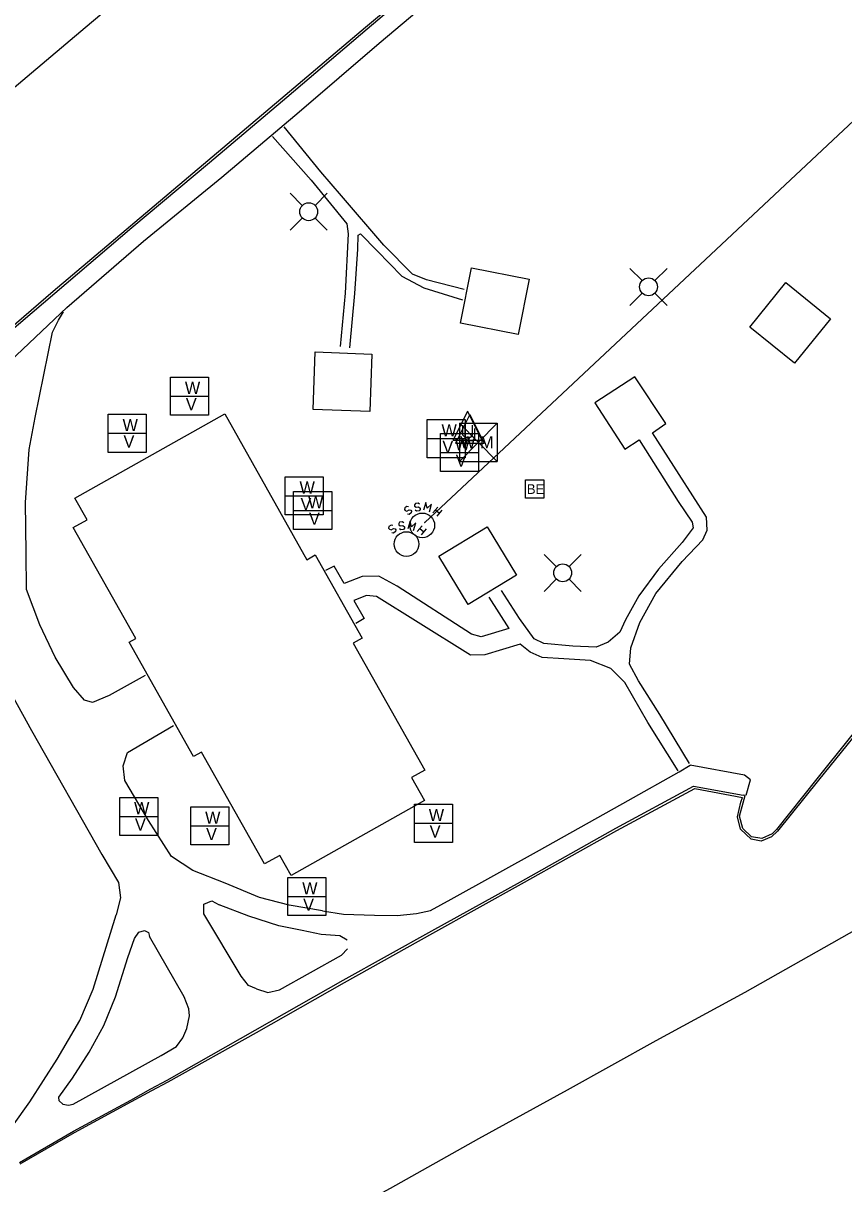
# Model space of a CAD drawing. Extents: x 1042086 to 1119166, y 1916606 to 1927565.
# Drawn here: x 1043119 to 1043321.6, y 1926246.9 to 1926533.5 of the extents above; entities that cross this region are included whole.
import ezdxf

# ---------------------------------------------------------------- set-up
doc = ezdxf.new("R2010")
doc.units = 0
for name, color, linetype in [('S_BUILDING', 7, 'Continuous'), ('S_CURB', 7, 'Continuous'), ('S_EDGE_PAVEMENT', 7, 'Continuous'), ('S_ELECTRIC_UTILITIES', 7, 'Continuous'), ('S_SANITARY_SEWER', 7, 'Continuous'), ('S_SIDEWALK', 7, 'Continuous'), ('S_UNDERGROUND_CABLE', 7, 'Continuous'), ('S_UTILITY_POLE', 7, 'Continuous'), ('S_UTL_PT_SYM', 7, 'Continuous'), ('S_WATER_UTILITIES', 7, 'Continuous')]:
    doc.layers.add(name, color=color, linetype=linetype)

msp = doc.modelspace()

# ---------------------------------------------------------------- linework, layer by layer
at = {"layer": 'S_BUILDING'}
for points in [[(1043241.2, 1926456.64), (1043226.98, 1926459.44), (1043229.68, 1926473.11), (1043243.9, 1926470.3)], [(1043309.4, 1926449.49), (1043298.39, 1926458.39), (1043307.29, 1926469.41), (1043318.31, 1926460.51)], [(1043190.58, 1926438.1), (1043191.11, 1926452.32), (1043205.08, 1926451.79), (1043204.55, 1926437.58)], [(1043178.6, 1926325.86), (1043163.01, 1926353.51), (1043161.04, 1926352.4), (1043145.14, 1926380.6), (1043146.84, 1926381.56), (1043131.39, 1926408.96), (1043134.77, 1926410.87), (1043131.79, 1926416.16), (1043168.75, 1926437), (1043189.05, 1926400.99), (1043191.11, 1926402.16), (1043202.7, 1926381.61), (1043200.48, 1926380.35), (1043218.14, 1926349.04), (1043214.89, 1926347.21), (1043218.08, 1926341.56), (1043185.15, 1926322.99), (1043182.34, 1926327.96)], [(1043228.86, 1926389.91), (1043221.62, 1926401.87), (1043233.58, 1926409.1), (1043240.82, 1926397.15)]]:
    msp.add_lwpolyline(points, close=True, dxfattribs=at)
at = {"layer": 'S_CURB'}
for points in [[(1043112.19, 1926454.4), (1043126.79, 1926466.85), (1043145.84, 1926483.04), (1043164.98, 1926499.12), (1043184.11, 1926515.22), (1043203.91, 1926532.06), (1043222.97, 1926548.25)], [(1043366.1, 1926416.39), (1043367.26, 1926414.66), (1043367.55, 1926413.33), (1043367.41, 1926412.29), (1043361.98, 1926405.29), (1043346.23, 1926385.88), (1043330.59, 1926366.38), (1043314.91, 1926346.91), (1043304.94, 1926334.4), (1043303.88, 1926333.32), (1043301.33, 1926332.15), (1043298.81, 1926332.56), (1043296.65, 1926334.61), (1043295.87, 1926337.66), (1043296.75, 1926340.95), (1043297.22, 1926342.73), (1043296.76, 1926342.83)], [(1043118.12, 1926252.12), (1043131.43, 1926259.9), (1043145.56, 1926267.51), (1043150.56, 1926270.32), (1043154.54, 1926272.51), (1043176.31, 1926284.81), (1043198.04, 1926297.17), (1043219.85, 1926309.38), (1043241.76, 1926321.41), (1043265.27, 1926334.69), (1043284.45, 1926345.09), (1043296.76, 1926342.83)]]:
    msp.add_lwpolyline(points, dxfattribs=at)
at = {"layer": 'S_EDGE_PAVEMENT'}
for points in [[(1042885.56, 1926337.32), (1042899.04, 1926343.23), (1042920.21, 1926356.51), (1042940.86, 1926370.65), (1042959.18, 1926385.04), (1042978.59, 1926400.81), (1042997.79, 1926416.81), (1043019.29, 1926434.74), (1043038.53, 1926450.69), (1043056.99, 1926467.43), (1043076.46, 1926483.12), (1043095.44, 1926499.39), (1043115.21, 1926516.28), (1043134.32, 1926532.4), (1043153.39, 1926548.56)], [(1043111.86, 1926454.8), (1043126.38, 1926467.34), (1043145.47, 1926483.48), (1043183.68, 1926515.73), (1043203.53, 1926532.51), (1043222.69, 1926548.57)], [(1043366.61, 1926416.77), (1043367.8, 1926415.07), (1043368.17, 1926413.35), (1043368.1, 1926412.3), (1043362.43, 1926404.93), (1043346.84, 1926385.39), (1043331.05, 1926366), (1043315.37, 1926346.53), (1043305.25, 1926333.99), (1043303.73, 1926332.56), (1043301.19, 1926331.5), (1043298.69, 1926331.97), (1043296.12, 1926334.45), (1043295.32, 1926337.5), (1043296.15, 1926341.11), (1043296.56, 1926342.25)], [(1043102.91, 1926186.56), (1043122.35, 1926197.07), (1043144.15, 1926209.32), (1043166.01, 1926221.45), (1043187.73, 1926233.83), (1043209.7, 1926245.77), (1043231.46, 1926258.09), (1043253.4, 1926270.06), (1043275.25, 1926282.23), (1043297.21, 1926294.17), (1043326.74, 1926310.95), (1043348.54, 1926323.19), (1043370.32, 1926335.48), (1043392.17, 1926347.63), (1043414.02, 1926359.78), (1043436.24, 1926372.23), (1043453.57, 1926381.87)], [(1043118.3, 1926251.81), (1043131.64, 1926259.54), (1043145.75, 1926267.17), (1043150.77, 1926269.93), (1043154.77, 1926272.1), (1043176.6, 1926284.28), (1043198.37, 1926296.56), (1043220.17, 1926308.81), (1043242.01, 1926320.95), (1043265.57, 1926334.14), (1043284.77, 1926344.5), (1043296.56, 1926342.25)]]:
    msp.add_lwpolyline(points, dxfattribs=at)
at = {"layer": 'S_ELECTRIC_UTILITIES'}
msp.add_lwpolyline([(1043243.03, 1926416.19), (1043243.03, 1926420.69), (1043247.53, 1926420.69), (1043247.53, 1926416.19)], close=True, dxfattribs=at)
at = {"layer": 'S_SANITARY_SEWER'}
for p, q in [((1043379.23, 1926561.23), (1043218.13, 1926410.22)), ((1043213.19, 1926413.78), (1043213.12, 1926413.39)), ((1043213.12, 1926413.39), (1043213.31, 1926413.12)), ((1043213.74, 1926414.17), (1043213.19, 1926413.78)), ((1043213.31, 1926413.12), (1043213.74, 1926413)), ((1043214.16, 1926414.09), (1043213.74, 1926414.17)), ((1043213.74, 1926413), (1043214.28, 1926413.35)), ((1043214.28, 1926412.19), (1043213.89, 1926412.27)), ((1043214.28, 1926413.35), (1043214.74, 1926413.27)), ((1043214.82, 1926412.58), (1043214.28, 1926412.19)), ((1043214.74, 1926413.27), (1043214.9, 1926413)), ((1043214.9, 1926413), (1043214.82, 1926412.58)), ((1043220.17, 1926412.54), (1043221.41, 1926414.01)), ((1043220.83, 1926413.31), (1043221.8, 1926412.5)), ((1043222.38, 1926413.2), (1043221.14, 1926411.72)), ((1043209.31, 1926409.16), (1043209.23, 1926408.77)), ((1043209.85, 1926409.55), (1043209.31, 1926409.16)), ((1043210.28, 1926409.47), (1043209.85, 1926409.55)), ((1043216.28, 1926407.92), (1043217.52, 1926409.39)), ((1043209.23, 1926408.77), (1043209.42, 1926408.5)), ((1043209.42, 1926408.5), (1043209.85, 1926408.39)), ((1043209.85, 1926408.39), (1043210.39, 1926408.74)), ((1043210.39, 1926407.57), (1043210, 1926407.65)), ((1043210.39, 1926408.74), (1043210.86, 1926408.66)), ((1043210.93, 1926407.96), (1043210.39, 1926407.57)), ((1043210.86, 1926408.66), (1043211.01, 1926408.39)), ((1043211.01, 1926408.39), (1043210.93, 1926407.96)), ((1043216.94, 1926408.7), (1043217.91, 1926407.88)), ((1043218.49, 1926408.58), (1043217.25, 1926407.11))]:
    msp.add_line(p, q, dxfattribs=at)
for points in [[(1043216.84, 1926414.71), (1043216.49, 1926414.98), (1043215.83, 1926414.9), (1043215.6, 1926414.55), (1043215.64, 1926414.24), (1043215.98, 1926413.93), (1043216.6, 1926414.05), (1043216.99, 1926413.74), (1043217.03, 1926413.43), (1043216.76, 1926413.04), (1043216.14, 1926412.96), (1043215.79, 1926413.24)], [(1043219.28, 1926412.85), (1043219.82, 1926414.71), (1043218.77, 1926413.7), (1043218.39, 1926415.13), (1043217.84, 1926413.27)], [(1043212.95, 1926410.09), (1043212.6, 1926410.36), (1043211.94, 1926410.29), (1043211.71, 1926409.94), (1043211.75, 1926409.63), (1043212.1, 1926409.32), (1043212.72, 1926409.43), (1043213.1, 1926409.12), (1043213.14, 1926408.81), (1043212.87, 1926408.43), (1043212.25, 1926408.35), (1043211.9, 1926408.62)], [(1043215.39, 1926408.23), (1043215.93, 1926410.09), (1043214.89, 1926409.08), (1043214.5, 1926410.52), (1043213.96, 1926408.66)]]:
    msp.add_lwpolyline(points, dxfattribs=at)
for centre in [(1043217.52, 1926409.47), (1043213.63, 1926404.86)]:
    msp.add_circle(centre, 3.05, dxfattribs=at)
at = {"layer": 'S_SIDEWALK'}
for points in [[(1043115.83, 1926450.03), (1043129.78, 1926463.26), (1043148.69, 1926479.62), (1043168.02, 1926495.48), (1043187.14, 1926511.58), (1043206.87, 1926528.51), (1043225.94, 1926544.68)], [(1043192.49, 1926496.76), (1043183.45, 1926507.88)], [(1043190.09, 1926494.72), (1043180.52, 1926505.53)], [(1043227.88, 1926467.69), (1043218.55, 1926470.12), (1043215.14, 1926471.53), (1043208.08, 1926478.63), (1043197.58, 1926490.81), (1043192.49, 1926496.76)], [(1043190.09, 1926494.72), (1043198.9, 1926483.9), (1043199.21, 1926481.47), (1043198.52, 1926466.78), (1043197.27, 1926453.65)], [(1043199.66, 1926453.35), (1043200.84, 1926466.75), (1043201.6, 1926477.64), (1043201.71, 1926481.13), (1043202.28, 1926481.47), (1043206.38, 1926477.3), (1043212.48, 1926471), (1043217.95, 1926468.11), (1043227.43, 1926465.19)], [(1043121.95, 1926436.13), (1043126.25, 1926457.17), (1043127.73, 1926460.14), (1043128.98, 1926462.17)], [(1043276.18, 1926362.73), (1043270.94, 1926371.11), (1043268.66, 1926375.21), (1043269.04, 1926379.23), (1043271.21, 1926385.53), (1043275.19, 1926392.67), (1043281.71, 1926400.56), (1043286.76, 1926405.88), (1043287.82, 1926408.27), (1043287.67, 1926411.46), (1043280.92, 1926422.05), (1043274.32, 1926432.34), (1043277.62, 1926434.61), (1043270.03, 1926446.19), (1043260.13, 1926439.74), (1043267.49, 1926428.31), (1043271.05, 1926430.59)], [(1043149.11, 1926372.38), (1043140.22, 1926367.46), (1043136.14, 1926365.76), (1043134.13, 1926366.28), (1043131.46, 1926369.41), (1043126.89, 1926376.94), (1043123.12, 1926384.91), (1043119.86, 1926393.61), (1043119.71, 1926402.68), (1043119.56, 1926415.09), (1043120.47, 1926428.19), (1043121.95, 1926436.13)], [(1043271.05, 1926430.59), (1043280.73, 1926415.41), (1043284.18, 1926410.24), (1043284.41, 1926408.84), (1043281.67, 1926405.23), (1043275.8, 1926398.7), (1043271.02, 1926392.06), (1043267.72, 1926386.18), (1043266.27, 1926383.1), (1043263.39, 1926380.6), (1043260.43, 1926379.42), (1043254.7, 1926379.61), (1043247.54, 1926380.29), (1043245.18, 1926381.43), (1043241.5, 1926386.44), (1043237.07, 1926393.43)], [(1043233.96, 1926391.71), (1043238.9, 1926384.04), (1043232.03, 1926381.96), (1043229.64, 1926382.6), (1043211.36, 1926394.44), (1043206.77, 1926396.91), (1043202.71, 1926396.87), (1043198.23, 1926395.13), (1043195.8, 1926399.38), (1043193.6, 1926398.32)], [(1043273.17, 1926360.82), (1043267.5, 1926370.64), (1043264.05, 1926374.14), (1043259.04, 1926376.11), (1043252.51, 1926376.53), (1043247.13, 1926376.87), (1043244.17, 1926378.16), (1043241.7, 1926380.1), (1043232.98, 1926377.51), (1043229.41, 1926377.44), (1043216.52, 1926385.52), (1043206.26, 1926391.95), (1043203.73, 1926392.17), (1043200.62, 1926390.95), (1043203.2, 1926386.44), (1043201.11, 1926385.24)], [(1043065.34, 1926384.3), (1043079.28, 1926383.96), (1043091.23, 1926382.71), (1043104.84, 1926380.47), (1043108.9, 1926378.83), (1043111.71, 1926375.68), (1043121.04, 1926358.83), (1043138.45, 1926328.23), (1043142.51, 1926321.25), (1043143.01, 1926317.49), (1043141.95, 1926313.31)], [(1043280.69, 1926348.82), (1043273.17, 1926360.82)], [(1043283.53, 1926350.65), (1043276.18, 1926362.73)], [(1043168.89, 1926321.12), (1043160.87, 1926324.21), (1043155.64, 1926327.74), (1043149.98, 1926336.58), (1043144.07, 1926346.45), (1043143.69, 1926350.1), (1043144.79, 1926353.4), (1043156.13, 1926360.08)], [(1043192.86, 1926314.31), (1043198.11, 1926313.47), (1043205.73, 1926313.23), (1043211.3, 1926313.13), (1043216.07, 1926313.62), (1043219.58, 1926314.33), (1043224.67, 1926317.19), (1043246.49, 1926329.27), (1043268.37, 1926341.53), (1043280.91, 1926348.58), (1043283.65, 1926350.29)], [(1043297.46, 1926342.85), (1043298.51, 1926346.66), (1043297.09, 1926347.78), (1043283.65, 1926350.29)], [(1043192.86, 1926314.31), (1043184.63, 1926315.68), (1043177.33, 1926317.61), (1043168.89, 1926321.12)], [(1043163.61, 1926313.57), (1043163.64, 1926315.93), (1043165.54, 1926316.73), (1043167.37, 1926315.76)], [(1043199, 1926307.03), (1043197.2, 1926308.1), (1043192.55, 1926308.46), (1043187.86, 1926309.42), (1043182.11, 1926310.6), (1043174.7, 1926312.99), (1043167.37, 1926315.76)], [(1043116.36, 1926261.1), (1043120.63, 1926267.1), (1043127.41, 1926277.64), (1043132.98, 1926287.19), (1043136.28, 1926294.98), (1043141.95, 1926313.31)], [(1043176.63, 1926295.04), (1043174.64, 1926295.82), (1043172.83, 1926298.19), (1043163.61, 1926313.57)], [(1043128.77, 1926266.56), (1043127.92, 1926267.35), (1043127.81, 1926268.26), (1043131.22, 1926272.98), (1043135.34, 1926279.37), (1043138.89, 1926286), (1043141.8, 1926293.05), (1043144.81, 1926302.73), (1043146.49, 1926307.49), (1043147.57, 1926309.03)], [(1043147.57, 1926309.03), (1043148.92, 1926309.44), (1043149.91, 1926308.91), (1043150.2, 1926307.98)], [(1043160.05, 1926288.37), (1043159.94, 1926290.1), (1043158.76, 1926293.06), (1043150.2, 1926307.98)], [(1043176.63, 1926295.04), (1043179.44, 1926294.16), (1043182.3, 1926294.76), (1043197.61, 1926303.35), (1043199.08, 1926304.89)], [(1043128.77, 1926266.56), (1043130.22, 1926266.33), (1043131.35, 1926266.52), (1043153.09, 1926278.57), (1043156.87, 1926280.76), (1043158.43, 1926282.94), (1043159.44, 1926285.25), (1043160.05, 1926288.37)]]:
    msp.add_lwpolyline(points, dxfattribs=at)
at = {"layer": 'S_UNDERGROUND_CABLE'}
for p, q in [((1043228.71, 1926437.65), (1043225.18, 1926430.55)), ((1043229.3, 1926436.83), (1043225.77, 1926429.74)), ((1043228.71, 1926437.65), (1043232.19, 1926430.55)), ((1043229.3, 1926436.83), (1043232.78, 1926429.74)), ((1043227.51, 1926431.79), (1043227.51, 1926434.24)), ((1043228.09, 1926430.98), (1043228.09, 1926433.42)), ((1043229.87, 1926434.24), (1043229.87, 1926431.79)), ((1043230.46, 1926433.42), (1043230.46, 1926430.98)), ((1043225.18, 1926430.55), (1043232.19, 1926430.55)), ((1043225.77, 1926429.74), (1043232.78, 1926429.74)), ((1043228.13, 1926431.14), (1043227.51, 1926431.79)), ((1043228.71, 1926430.32), (1043228.09, 1926430.98)), ((1043229.33, 1926431.14), (1043228.13, 1926431.14)), ((1043229.92, 1926430.32), (1043228.71, 1926430.32)), ((1043229.87, 1926431.79), (1043229.33, 1926431.14)), ((1043230.46, 1926430.98), (1043229.92, 1926430.32))]:
    msp.add_line(p, q, dxfattribs=at)
at = {"layer": 'S_UTILITY_POLE'}
for p, q in [((1043187.89, 1926488.5), (1043184.91, 1926491.48)), ((1043191.07, 1926488.5), (1043194.05, 1926491.48)), ((1043187.89, 1926485.32), (1043184.91, 1926482.34)), ((1043191.07, 1926485.32), (1043194.05, 1926482.34)), ((1043271.78, 1926469.96), (1043268.8, 1926472.94)), ((1043274.96, 1926469.96), (1043277.94, 1926472.94)), ((1043271.78, 1926466.78), (1043268.8, 1926463.8)), ((1043274.96, 1926466.78), (1043277.94, 1926463.8)), ((1043250.59, 1926399.33), (1043247.61, 1926402.32)), ((1043253.77, 1926399.33), (1043256.75, 1926402.32)), ((1043250.59, 1926396.16), (1043247.61, 1926393.17)), ((1043253.77, 1926396.16), (1043256.75, 1926393.17))]:
    msp.add_line(p, q, dxfattribs=at)
for centre in [(1043189.49, 1926486.92), (1043273.38, 1926468.38), (1043252.19, 1926397.75)]:
    msp.add_circle(centre, 2.21, dxfattribs=at)
at = {"layer": 'S_UTL_PT_SYM'}
msp.add_lwpolyline([(1043218.13, 1926410.22), (1043218.13, 1926410.27), (1043218.13, 1926410.22), (1043218.08, 1926410.22), (1043218.13, 1926410.22), (1043218.13, 1926410.17), (1043218.13, 1926410.22), (1043218.18, 1926410.22)], dxfattribs=at)
at = {"layer": 'S_WATER_UTILITIES'}
for p, q in [((1043155.38, 1926446.11), (1043164.79, 1926446.11)), ((1043155.38, 1926436.7), (1043155.38, 1926446.11)), ((1043164.79, 1926446.11), (1043164.79, 1926436.7)), ((1043155.38, 1926441.42), (1043164.79, 1926441.42)), ((1043140, 1926436.9), (1043149.41, 1926436.9)), ((1043140, 1926427.49), (1043140, 1926436.9)), ((1043149.41, 1926436.9), (1043149.41, 1926427.49)), ((1043164.79, 1926436.7), (1043155.38, 1926436.7)), ((1043218.71, 1926435.6), (1043228.13, 1926435.6)), ((1043218.71, 1926426.19), (1043218.71, 1926435.6)), ((1043228.13, 1926435.6), (1043228.13, 1926426.19)), ((1043140, 1926432.21), (1043149.41, 1926432.21)), ((1043221.99, 1926432.18), (1043231.41, 1926432.18)), ((1043221.99, 1926422.77), (1043221.99, 1926432.18)), ((1043226.68, 1926434.74), (1043236.02, 1926434.74)), ((1043226.68, 1926434.74), (1043226.68, 1926425.24)), ((1043226.68, 1926434.74), (1043236.02, 1926425.24)), ((1043236.02, 1926434.74), (1043226.68, 1926425.24)), ((1043231.41, 1926432.18), (1043231.41, 1926422.77)), ((1043236.02, 1926434.74), (1043236.02, 1926425.24)), ((1043218.71, 1926430.91), (1043228.13, 1926430.91)), ((1043149.41, 1926427.49), (1043140, 1926427.49)), ((1043221.99, 1926427.49), (1043231.41, 1926427.49)), ((1043228.13, 1926426.19), (1043218.71, 1926426.19)), ((1043226.68, 1926425.24), (1043236.02, 1926425.24)), ((1043183.68, 1926421.48), (1043193.1, 1926421.48)), ((1043183.68, 1926412.06), (1043183.68, 1926421.48)), ((1043193.1, 1926421.48), (1043193.1, 1926412.06)), ((1043231.41, 1926422.77), (1043221.99, 1926422.77)), ((1043185.78, 1926417.84), (1043195.19, 1926417.84)), ((1043185.78, 1926408.43), (1043185.78, 1926417.84)), ((1043195.19, 1926417.84), (1043195.19, 1926408.43)), ((1043183.68, 1926416.79), (1043193.1, 1926416.79)), ((1043193.1, 1926412.06), (1043183.68, 1926412.06)), ((1043185.78, 1926413.15), (1043195.19, 1926413.15)), ((1043195.19, 1926408.43), (1043185.78, 1926408.43)), ((1043142.83, 1926342.31), (1043152.24, 1926342.31)), ((1043142.83, 1926332.89), (1043142.83, 1926342.31)), ((1043152.24, 1926342.31), (1043152.24, 1926332.89)), ((1043215.57, 1926340.59), (1043224.99, 1926340.59)), ((1043215.57, 1926331.18), (1043215.57, 1926340.59)), ((1043224.99, 1926340.59), (1043224.99, 1926331.18)), ((1043142.83, 1926337.62), (1043152.24, 1926337.62)), ((1043160.37, 1926339.97), (1043169.79, 1926339.97)), ((1043160.37, 1926330.55), (1043160.37, 1926339.97)), ((1043169.79, 1926339.97), (1043169.79, 1926330.55)), ((1043160.37, 1926335.28), (1043169.79, 1926335.28)), ((1043215.57, 1926335.91), (1043224.99, 1926335.91)), ((1043152.24, 1926332.89), (1043142.83, 1926332.89)), ((1043169.79, 1926330.55), (1043160.37, 1926330.55)), ((1043224.99, 1926331.18), (1043215.57, 1926331.18)), ((1043184.34, 1926322.51), (1043193.75, 1926322.51)), ((1043184.34, 1926313.1), (1043184.34, 1926322.51)), ((1043193.75, 1926322.51), (1043193.75, 1926313.1)), ((1043184.34, 1926317.82), (1043193.75, 1926317.82)), ((1043193.75, 1926313.1), (1043184.34, 1926313.1))]:
    msp.add_line(p, q, dxfattribs=at)

# ---------------------------------------------------------------- texts
at = {"layer": 'S_ELECTRIC_UTILITIES'}
msp.add_text('BE', height=2.4, rotation=360, dxfattribs=at).set_placement((1043243.35, 1926417.24))
at = {"layer": 'S_WATER_UTILITIES'}
for s, p in [('W', (1043158.93, 1926441.95)), ('V', (1043159.17, 1926437.89)), ('W', (1043143.55, 1926432.74)), ('W', (1043222.27, 1926431.45)), ('V', (1043143.78, 1926428.68)), ('V', (1043222.5, 1926427.38)), ('W', (1043225.54, 1926428.03)), ('W M', (1043226.89, 1926428.5)), ('V', (1043225.78, 1926423.96)), ('W', (1043187.23, 1926417.32)), ('V', (1043187.47, 1926413.26)), ('W', (1043189.33, 1926413.69)), ('V', (1043189.56, 1926409.62)), ('W', (1043146.38, 1926338.15)), ('W', (1043163.92, 1926335.81)), ('W', (1043219.13, 1926336.44)), ('V', (1043146.61, 1926334.09)), ('V', (1043164.16, 1926331.75)), ('V', (1043219.36, 1926332.37)), ('W', (1043187.89, 1926318.36)), ('V', (1043188.12, 1926314.29))]:
    msp.add_text(s, height=3, rotation=360, dxfattribs=at).set_placement(p)

doc.saveas('drawing.dxf')
